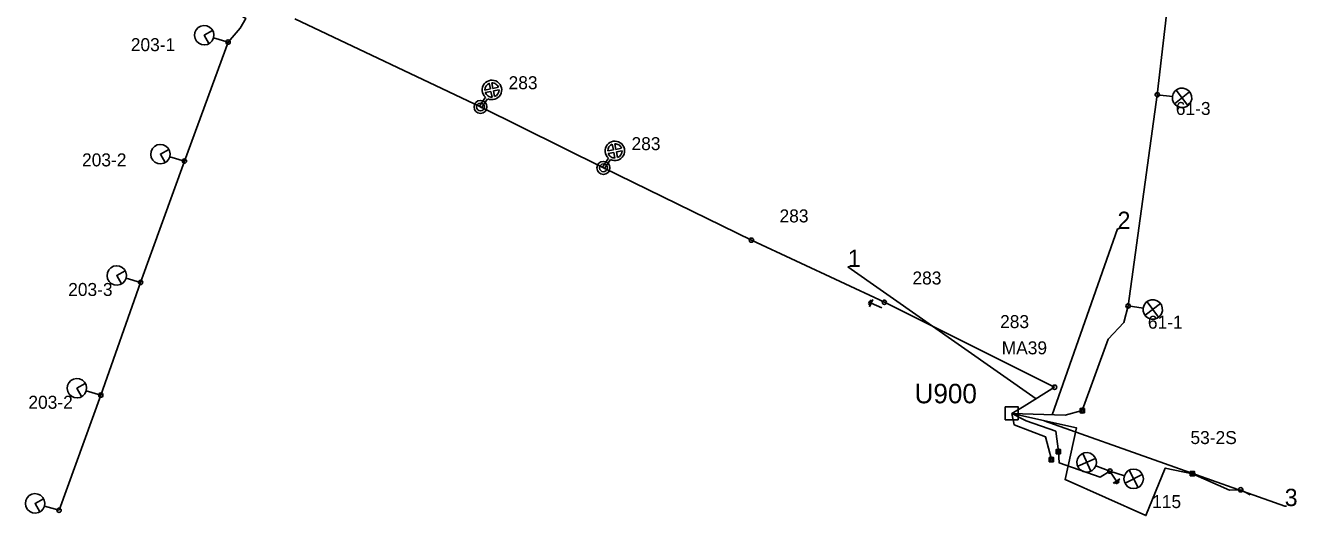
# Model space of a CAD drawing. Extents: x 25497851 to 25498523, y 6686544 to 6687372.
# Drawn here: x 25498185 to 25498478.8, y 6686764.8 to 6686878 of the extents above; entities that cross this region are included whole.
import ezdxf

# ---------------------------------------------------------------- set-up
doc = ezdxf.new("R2010")
doc.units = 0
for name, color, linetype in [('EL_CABLE_ILMA', 7, 'Continuous'), ('EL_CABLE_MAA', 7, 'Continuous'), ('KEYGWT_ANNOTATION', 7, 'Continuous'), ('Level 15', 7, 'Continuous'), ('Level 17', 7, 'Continuous'), ('Level 4', 7, 'Continuous'), ('Level 42', 7, 'Continuous'), ('Level 63', 7, 'Continuous'), ('PYLVAS', 7, 'Continuous'), ('Taso 1', 7, 'Continuous'), ('VALAISIN', 7, 'Continuous')]:
    doc.layers.add(name, color=color, linetype=linetype)

msp = doc.modelspace()

# ---------------------------------------------------------------- linework, layer by layer
at = {"layer": 'EL_CABLE_ILMA'}
for points in [[(25498446.61, 6686862.01), (25498452.51, 6686913.14)], [(25498439.87, 6686813.21), (25498446.61, 6686862.01)], [(25498465.88, 6686770.72), (25498468.07, 6686769.58)]]:
    msp.add_lwpolyline(points, dxfattribs=at)
at = {"layer": 'EL_CABLE_MAA'}
for points in [[(25498231.88, 6686874.15), (25498234.67, 6686877.37), (25498236.01, 6686879.59), (25498212.63, 6686893.9), (25498209.99, 6686900.07)], [(25498290.21, 6686859.18), (25498247.33, 6686879.52)], [(25498221.78, 6686846.67), (25498231.88, 6686874.15)], [(25498318.62, 6686845.1), (25498290.21, 6686859.18)], [(25498211.67, 6686818.65), (25498221.78, 6686846.67)], [(25498352.82, 6686828.4), (25498318.62, 6686845.1)], [(25498383.53, 6686814.06), (25498352.82, 6686828.4)], [(25498202.47, 6686792.59), (25498211.67, 6686818.65)], [(25498422.86, 6686794.43), (25498383.53, 6686814.06)], [(25498429.26, 6686789.01), (25498435.28, 6686805.53), (25498438.91, 6686809.36), (25498439.87, 6686813.21)], [(25498412.97, 6686788.38), (25498415.85, 6686790.03), (25498422.86, 6686794.43)], [(25498192.82, 6686765.99), (25498202.47, 6686792.59)], [(25498412.97, 6686788.38), (25498425.31, 6686787.98), (25498429.26, 6686789.01)], [(25498412.97, 6686788.38), (25498427.95, 6686785.01), (25498425.31, 6686773.1), (25498443.96, 6686764.77), (25498448.46, 6686775.75), (25498454.73, 6686774.45)], [(25498412.97, 6686788.38), (25498416.28, 6686786.63), (25498423.16, 6686784.24), (25498423.74, 6686779.54)], [(25498412.97, 6686788.38), (25498413.51, 6686785.74), (25498420.78, 6686782.96), (25498422.15, 6686777.69)], [(25498423.74, 6686779.54), (25498423.9, 6686776.97), (25498433.43, 6686773.67), (25498435.67, 6686775.03)], [(25498454.73, 6686774.45), (25498463.26, 6686770.6), (25498465.88, 6686770.72)]]:
    msp.add_lwpolyline(points, dxfattribs=at)
at = {"layer": 'KEYGWT_ANNOTATION'}
for points in [[(25498422.34, 6686788.07), (25498437.42, 6686830.99)], [(25498437.42, 6686830.99), (25498437.82, 6686830.99)], [(25498418.62, 6686791.76), (25498375.1, 6686822.22)], [(25498375.1, 6686822.22), (25498375.5, 6686822.22)], [(25498420.47, 6686786.69), (25498476.05, 6686766.96)], [(25498476.05, 6686766.96), (25498476.45, 6686766.96)]]:
    msp.add_lwpolyline(points, dxfattribs=at)
at = {"layer": 'Level 15'}
for points in [[(25498429.75, 6686788.51), (25498429.75, 6686789.5), (25498428.76, 6686789.5), (25498428.76, 6686788.51)], [(25498424.23, 6686779.04), (25498424.23, 6686780.04), (25498423.24, 6686780.04), (25498423.24, 6686779.04)], [(25498422.65, 6686777.19), (25498422.65, 6686778.18), (25498421.65, 6686778.18), (25498421.65, 6686777.19)], [(25498454.24, 6686773.96), (25498455.23, 6686773.96), (25498455.23, 6686774.95), (25498454.24, 6686774.95)]]:
    msp.add_lwpolyline(points, close=True, dxfattribs=at)
at = {"layer": 'Level 17'}
for points in [[(25498380.15, 6686814.41), (25498380.01, 6686814.07)], [(25498380.25, 6686813.96), (25498380.52, 6686814.58)], [(25498380.48, 6686813.85), (25498380.85, 6686814.72)], [(25498380.01, 6686814.07), (25498379.86, 6686813.73)], [(25498379.98, 6686813.35), (25498380.25, 6686813.96)], [(25498380.1, 6686812.98), (25498380.48, 6686813.85)], [(25498382.99, 6686812.77), (25498380.48, 6686813.86)], [(25498435.67, 6686775.03), (25498437.17, 6686772.75)], [(25498437.97, 6686773.27), (25498437.18, 6686772.75)], [(25498437.18, 6686772.75), (25498436.39, 6686772.23)], [(25498437.31, 6686772.53), (25498436.75, 6686772.16)], [(25498437.14, 6686772.11), (25498437.45, 6686772.31)], [(25498437.87, 6686772.9), (25498437.31, 6686772.53)], [(25498437.45, 6686772.31), (25498437.76, 6686772.52)]]:
    msp.add_lwpolyline(points, dxfattribs=at)
at = {"layer": 'Level 4'}
for points in [[(25498429.26, 6686788.39), (25498429.55, 6686789), (25498429.26, 6686789.63), (25498428.96, 6686789), (25498429.26, 6686788.39)], [(25498423.74, 6686778.92), (25498424.03, 6686779.54), (25498423.74, 6686780.16), (25498423.45, 6686779.54), (25498423.74, 6686778.92)], [(25498422.15, 6686777.07), (25498422.44, 6686777.68), (25498422.15, 6686778.31), (25498421.86, 6686777.68), (25498422.15, 6686777.07)], [(25498454.12, 6686774.45), (25498454.73, 6686774.16), (25498455.35, 6686774.45), (25498454.73, 6686774.75), (25498454.12, 6686774.45)]]:
    msp.add_lwpolyline(points, dxfattribs=at)
at = {"layer": 'Level 42'}
msp.add_lwpolyline([(25498414.46, 6686786.89), (25498414.46, 6686789.87), (25498411.49, 6686789.87), (25498411.49, 6686786.89)], close=True, dxfattribs=at)
at = {"layer": 'PYLVAS'}
for centre, radius in [((25498290.21, 6686859.18), 1.5), ((25498290.21, 6686859.18), 0.9), ((25498318.62, 6686845.1), 1.5), ((25498318.62, 6686845.1), 0.9)]:
    msp.add_circle(centre, radius, dxfattribs=at)
at = {"layer": 'Taso 1'}
for p, q in [((25498228.52, 6686875.13), (25498231.88, 6686874.15)), ((25498450.09, 6686861.57), (25498446.61, 6686862.01)), ((25498454.07, 6686862.65), (25498450.56, 6686859.92)), ((25498453.68, 6686859.53), (25498450.96, 6686863.04)), ((25498218.41, 6686847.65), (25498221.78, 6686846.67)), ((25498208.31, 6686819.62), (25498211.67, 6686818.65)), ((25498443.33, 6686812.72), (25498439.87, 6686813.21)), ((25498447.34, 6686813.73), (25498443.78, 6686811.07)), ((25498446.89, 6686810.62), (25498444.23, 6686814.18)), ((25498199.11, 6686793.57), (25498202.47, 6686792.59)), ((25498429.38, 6686779.09), (25498431.21, 6686775.04)), ((25498428.27, 6686776.15), (25498432.32, 6686777.98)), ((25498432.4, 6686776.27), (25498435.67, 6686775.03)), ((25498439, 6686773.95), (25498435.67, 6686775.03)), ((25498443.12, 6686774.26), (25498439.16, 6686772.25)), ((25498442.15, 6686771.28), (25498440.13, 6686775.24)), ((25498189.46, 6686766.96), (25498192.82, 6686765.99))]:
    msp.add_line(p, q, dxfattribs=at)
for points in [[(25498224.2, 6686876.38), (25498224.11, 6686875.68), (25498224.24, 6686874.99), (25498224.58, 6686874.38), (25498225.09, 6686873.89), (25498225.73, 6686873.59), (25498226.43, 6686873.51), (25498227.12, 6686873.64), (25498227.74, 6686873.98), (25498228.22, 6686874.49), (25498228.52, 6686875.13), (25498228.61, 6686875.83), (25498228.48, 6686876.52), (25498228.14, 6686877.13), (25498227.62, 6686877.62), (25498226.99, 6686877.92), (25498226.29, 6686878), (25498225.6, 6686877.87), (25498224.98, 6686877.53), (25498224.5, 6686877.02)], [(25498454.55, 6686861), (25498454.53, 6686861.71), (25498454.29, 6686862.37), (25498453.86, 6686862.93), (25498453.28, 6686863.32), (25498452.6, 6686863.52), (25498451.9, 6686863.5), (25498451.24, 6686863.26), (25498450.68, 6686862.83), (25498450.28, 6686862.24), (25498450.09, 6686861.57), (25498450.11, 6686860.86), (25498450.35, 6686860.2), (25498450.78, 6686859.65), (25498451.36, 6686859.25), (25498452.04, 6686859.05), (25498452.74, 6686859.08), (25498453.4, 6686859.31), (25498453.96, 6686859.75), (25498454.35, 6686860.33)], [(25498214.09, 6686848.9), (25498214.01, 6686848.21), (25498214.14, 6686847.51), (25498214.48, 6686846.9), (25498214.99, 6686846.42), (25498215.63, 6686846.12), (25498216.32, 6686846.03), (25498217.02, 6686846.16), (25498217.63, 6686846.5), (25498218.11, 6686847.01), (25498218.41, 6686847.65), (25498218.5, 6686848.35), (25498218.37, 6686849.04), (25498218.03, 6686849.66), (25498217.52, 6686850.14), (25498216.88, 6686850.44), (25498216.18, 6686850.53), (25498215.49, 6686850.39), (25498214.88, 6686850.05), (25498214.39, 6686849.54)], [(25498203.99, 6686820.88), (25498203.9, 6686820.18), (25498204.03, 6686819.49), (25498204.37, 6686818.87), (25498204.88, 6686818.39), (25498205.52, 6686818.09), (25498206.22, 6686818), (25498206.91, 6686818.14), (25498207.52, 6686818.47), (25498208.01, 6686818.99), (25498208.31, 6686819.62), (25498208.39, 6686820.32), (25498208.26, 6686821.01), (25498207.92, 6686821.63), (25498207.41, 6686822.11), (25498206.77, 6686822.41), (25498206.08, 6686822.5), (25498205.38, 6686822.37), (25498204.77, 6686822.03), (25498204.29, 6686821.52)], [(25498447.79, 6686812.08), (25498447.77, 6686812.79), (25498447.55, 6686813.45), (25498447.12, 6686814.02), (25498446.55, 6686814.42), (25498445.88, 6686814.63), (25498445.17, 6686814.62), (25498444.51, 6686814.39), (25498443.94, 6686813.97), (25498443.54, 6686813.39), (25498443.33, 6686812.72), (25498443.34, 6686812.01), (25498443.57, 6686811.35), (25498443.99, 6686810.78), (25498444.57, 6686810.38), (25498445.24, 6686810.17), (25498445.95, 6686810.18), (25498446.61, 6686810.41), (25498447.17, 6686810.83), (25498447.58, 6686811.41)], [(25498194.79, 6686794.82), (25498194.7, 6686794.12), (25498194.83, 6686793.43), (25498195.17, 6686792.82), (25498195.68, 6686792.33), (25498196.32, 6686792.03), (25498197.02, 6686791.95), (25498197.71, 6686792.08), (25498198.32, 6686792.42), (25498198.81, 6686792.93), (25498199.11, 6686793.57), (25498199.19, 6686794.27), (25498199.06, 6686794.96), (25498198.72, 6686795.57), (25498198.21, 6686796.06), (25498197.57, 6686796.35), (25498196.87, 6686796.44), (25498196.18, 6686796.31), (25498195.57, 6686795.97), (25498195.09, 6686795.46)], [(25498428.19, 6686777.86), (25498428.05, 6686777.17), (25498428.12, 6686776.47), (25498428.41, 6686775.83), (25498428.89, 6686775.31), (25498429.5, 6686774.96), (25498430.19, 6686774.82), (25498430.89, 6686774.89), (25498431.53, 6686775.18), (25498432.05, 6686775.66), (25498432.4, 6686776.27), (25498432.54, 6686776.96), (25498432.46, 6686777.66), (25498432.17, 6686778.3), (25498431.7, 6686778.82), (25498431.09, 6686779.17), (25498430.4, 6686779.31), (25498429.7, 6686779.23), (25498429.06, 6686778.95), (25498428.54, 6686778.47)], [(25498443.28, 6686772.56), (25498443.39, 6686773.26), (25498443.28, 6686773.95), (25498442.96, 6686774.58), (25498442.46, 6686775.08), (25498441.83, 6686775.4), (25498441.14, 6686775.51), (25498440.44, 6686775.4), (25498439.82, 6686775.08), (25498439.32, 6686774.58), (25498439, 6686773.95), (25498438.89, 6686773.26), (25498439, 6686772.56), (25498439.32, 6686771.93), (25498439.82, 6686771.44), (25498440.44, 6686771.12), (25498441.14, 6686771.01), (25498441.83, 6686771.12), (25498442.46, 6686771.44), (25498442.96, 6686771.93)], [(25498185.14, 6686768.22), (25498185.05, 6686767.52), (25498185.18, 6686766.83), (25498185.52, 6686766.21), (25498186.03, 6686765.73), (25498186.67, 6686765.43), (25498187.37, 6686765.34), (25498188.06, 6686765.48), (25498188.67, 6686765.81), (25498189.16, 6686766.33), (25498189.46, 6686766.96), (25498189.54, 6686767.66), (25498189.41, 6686768.35), (25498189.07, 6686768.97), (25498188.56, 6686769.45), (25498187.92, 6686769.75), (25498187.23, 6686769.84), (25498186.53, 6686769.71), (25498185.92, 6686769.37), (25498185.44, 6686768.86)]]:
    msp.add_lwpolyline(points, close=True, dxfattribs=at)
for points in [[(25498228.31, 6686876.83), (25498226.36, 6686875.76), (25498227.43, 6686873.81)], [(25498218.2, 6686849.35), (25498216.25, 6686848.28), (25498217.32, 6686846.33)], [(25498208.09, 6686821.32), (25498206.14, 6686820.25), (25498207.22, 6686818.3)], [(25498198.89, 6686795.27), (25498196.94, 6686794.19), (25498198.02, 6686792.25)], [(25498189.24, 6686768.66), (25498187.29, 6686767.59), (25498188.37, 6686765.64)]]:
    msp.add_lwpolyline(points, dxfattribs=at)
for centre in [(25498231.88, 6686874.15), (25498446.61, 6686862.01), (25498221.78, 6686846.67), (25498352.82, 6686828.4), (25498211.67, 6686818.65), (25498383.53, 6686814.06), (25498439.87, 6686813.21), (25498422.86, 6686794.43), (25498202.47, 6686792.59), (25498435.67, 6686775.03), (25498465.88, 6686770.72), (25498192.82, 6686765.99)]:
    msp.add_circle(centre, 0.5, dxfattribs=at)
at = {"layer": 'VALAISIN'}
for p, q in [((25498292.25, 6686864.65), (25498292.5, 6686863.35)), ((25498293.09, 6686863.46), (25498292.84, 6686864.76)), ((25498289.96, 6686859.34), (25498291.36, 6686861.43)), ((25498292.5, 6686863.35), (25498291.21, 6686863.09)), ((25498291.32, 6686862.5), (25498292.62, 6686862.76)), ((25498292.62, 6686862.76), (25498292.87, 6686861.46)), ((25498294.39, 6686863.72), (25498293.09, 6686863.46)), ((25498293.21, 6686862.87), (25498294.5, 6686863.13)), ((25498293.46, 6686861.58), (25498293.21, 6686862.87)), ((25498290.46, 6686859.01), (25498289.96, 6686859.34)), ((25498291.86, 6686861.09), (25498290.46, 6686859.01)), ((25498320.65, 6686850.57), (25498320.91, 6686849.27)), ((25498321.5, 6686849.38), (25498321.24, 6686850.68)), ((25498322.8, 6686849.64), (25498321.5, 6686849.38)), ((25498318.37, 6686845.26), (25498319.77, 6686847.35)), ((25498320.27, 6686847.01), (25498318.87, 6686844.93)), ((25498320.91, 6686849.27), (25498319.61, 6686849.01)), ((25498319.73, 6686848.42), (25498321.02, 6686848.68)), ((25498321.02, 6686848.68), (25498321.28, 6686847.38)), ((25498321.61, 6686848.79), (25498322.91, 6686849.05)), ((25498321.87, 6686847.5), (25498321.61, 6686848.79)), ((25498318.87, 6686844.93), (25498318.37, 6686845.26))]:
    msp.add_line(p, q, dxfattribs=at)
for centre, radius, start, end in [((25498292.86, 6686863.11), 2.25, 56.1117, 228.4495), ((25498292.86, 6686863.11), 1.65, 111.5874, 180.6361), ((25498292.86, 6686863.11), 2.25, 243.774, 56.1117), ((25498292.86, 6686863.11), 1.65, 56.1117, 90.6361), ((25498292.86, 6686863.11), 1.65, 21.5874, 56.1117), ((25498292.86, 6686863.11), 1.65, 201.5874, 236.1117), ((25498292.86, 6686863.11), 1.65, 236.1117, 270.6361), ((25498292.86, 6686863.11), 1.65, 291.5874, 0.6361), ((25498321.26, 6686849.03), 2.25, 56.1117, 228.4495), ((25498321.26, 6686849.03), 1.65, 111.5874, 180.6361), ((25498321.26, 6686849.03), 2.25, 243.774, 56.1117), ((25498321.26, 6686849.03), 1.65, 56.1117, 90.6361), ((25498321.26, 6686849.03), 1.65, 21.5874, 56.1117), ((25498321.26, 6686849.03), 1.65, 201.5874, 236.1117), ((25498321.26, 6686849.03), 1.65, 236.1117, 270.6361), ((25498321.26, 6686849.03), 1.65, 291.5874, 0.6361)]:
    msp.add_arc(centre, radius, start, end, dxfattribs=at)

# ---------------------------------------------------------------- texts
at = {"layer": 'KEYGWT_ANNOTATION'}
for s, height, p in [('203-1', 3, (25498209.4, 6686872.07)), ('283', 3, (25498296.7, 6686863.28)), ('61-3', 3, (25498450.89, 6686857.33)), ('283', 3, (25498325.11, 6686849.2)), ('203-2', 3, (25498198.13, 6686845.45)), ('283', 3, (25498359.31, 6686832.5)), ('2', 4, (25498437.42, 6686830.99)), ('1', 4, (25498375.1, 6686822.22)), ('283', 3, (25498390.02, 6686818.16)), ('203-3', 3, (25498194.93, 6686815.51)), ('283', 3, (25498410.28, 6686808.08)), ('61-1', 3, (25498444.43, 6686807.95)), ('MA39', 3, (25498410.65, 6686802.02)), ('U900', 4.5, (25498390.53, 6686790.71)), ('203-2', 3, (25498185.73, 6686789.45)), ('53-2S', 3, (25498454.27, 6686781.29)), ('3', 4, (25498476.05, 6686766.96)), ('115', 3, (25498445.42, 6686766.5))]:
    msp.add_text(s, height=height, dxfattribs=at).set_placement(p)
at = {"layer": 'Level 63'}
for s, height, rotation, p in [('(C) KEYPRO 2000', 0.0001, 246.6, (25498380.15, 6686814.41)), ('*C* KEYPRO 2003', 0.000401, 90, (25498414.46, 6686788.38)), ('*C* KEYPRO 2003', 0.0001, 90, (25498429.55, 6686789)), ('*C* KEYPRO 2003', 0.0001, 90, (25498429.75, 6686789)), ('*C* KEYPRO 2003', 0.0001, 90, (25498424.03, 6686779.53)), ('*C* KEYPRO 2003', 0.0001, 90, (25498424.23, 6686779.54)), ('*C* KEYPRO 2003', 0.0001, 90, (25498422.44, 6686777.68)), ('*C* KEYPRO 2003', 0.0001, 90, (25498422.65, 6686777.69)), ('(C) KEYPRO 2000', 0.0001, 33.3, (25498437.14, 6686772.11))]:
    msp.add_text(s, height=height, rotation=rotation, dxfattribs=at).set_placement(p)
for p in [(25498454.73, 6686774.16), (25498454.73, 6686773.96)]:
    msp.add_text('*C* KEYPRO 2003', height=0.0001, dxfattribs=at).set_placement(p)

doc.saveas('drawing.dxf')
